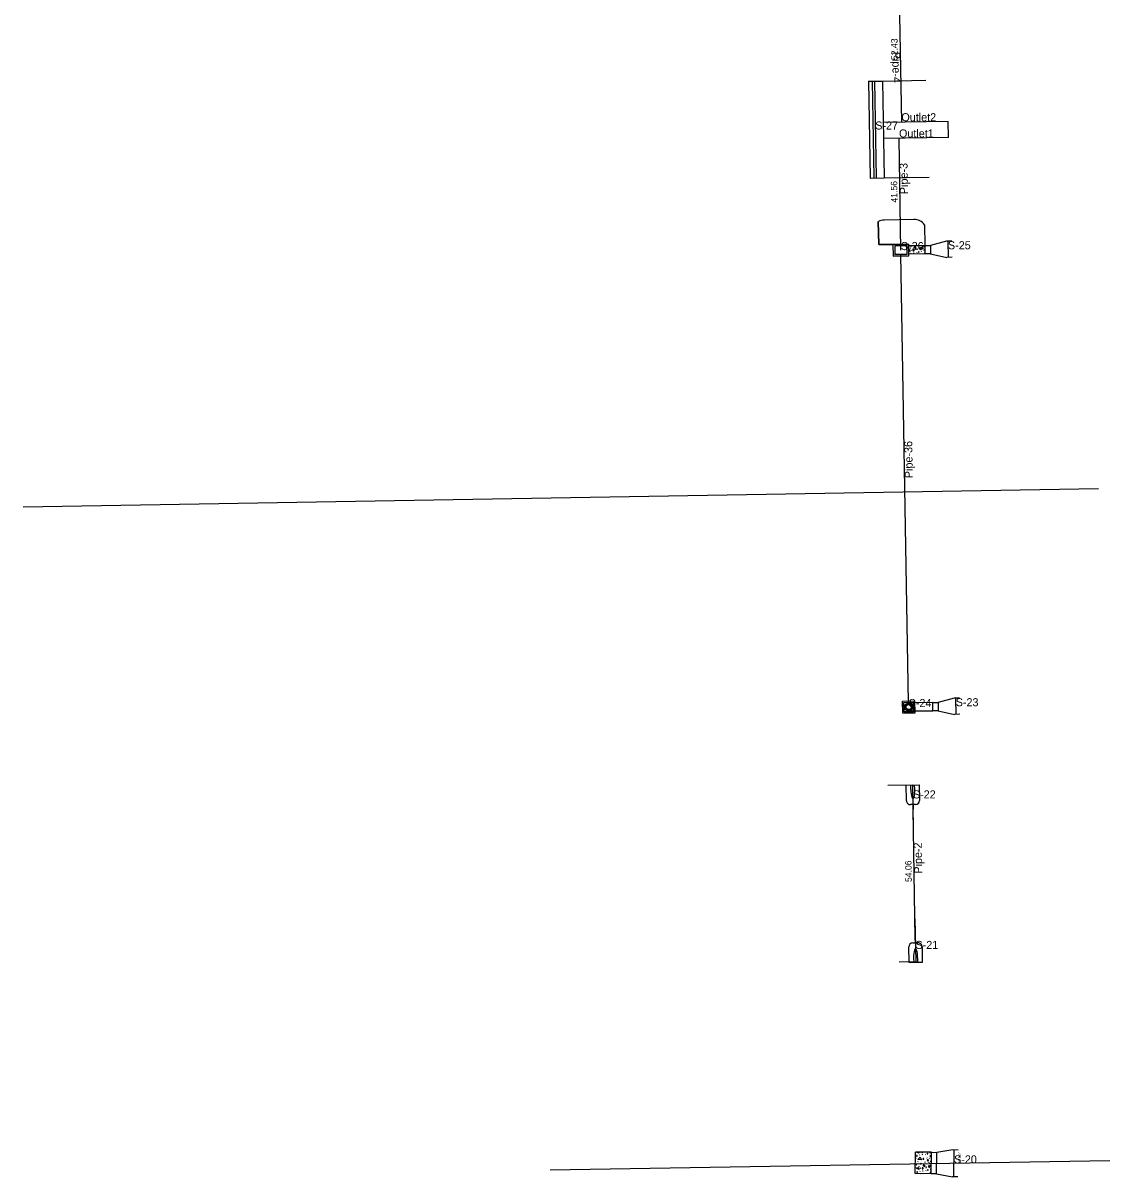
# Model space of a CAD drawing. Extents: x 925371 to 925937, y 853654 to 858024.
# Drawn here: x 925428.5 to 925832.9, y 854923.1 to 855352.2 of the extents above; entities that cross this region are included whole.
import ezdxf

# ---------------------------------------------------------------- set-up
doc = ezdxf.new("R2010")
doc.units = 0
for name, color, linetype in [('DitchPavt', 7, 'Continuous'), ('Endwall', 7, 'Continuous'), ('GPKDrBack_dp', 7, 'Continuous'), ('GPKDrBottom_dp', 7, 'Continuous'), ('GPKDrCellIns_dp', 7, 'Continuous'), ('GPKDrCentroid_dp', 7, 'Continuous'), ('GPKDrFront_dp', 7, 'Continuous'), ('GPKDrPipe_dp', 7, 'Continuous'), ('GPKDrPipeCir_dp', 7, 'Continuous'), ('InletBottomP', 7, 'Continuous'), ('InletClosedFlume', 7, 'Continuous'), ('InletDBI', 7, 'Continuous'), ('Manhole', 7, 'Continuous'), ('MES', 7, 'Continuous'), ('Miscellaneous5', 7, 'Continuous'), ('Miscellaneous6', 7, 'Continuous'), ('NonPlottingEle_dp', 7, 'Continuous'), ('PipeCulvert', 7, 'Continuous'), ('PipeCulvertSS', 7, 'Continuous'), ('Scratch1_dp', 7, 'Continuous')]:
    doc.layers.add(name, color=color, linetype=linetype)

msp = doc.modelspace()

# ---------------------------------------------------------------- linework, layer by layer
at = {"layer": 'DitchPavt'}
for p, q in [((925759.95, 855279.17), (925748.95, 855278.98)), ((925764.11, 855269.46), (925763.98, 855277.23)), ((925752.19, 855269.91), (925758.02, 855270.01)), ((925758.02, 855270.01), (925758.03, 855269.36)), ((925766.11, 855269.5), (925758.03, 855269.36)), ((925758.03, 855269.36), (925764.11, 855269.46)), ((925759.2, 855269.33), (925759.24, 855269.38)), ((925758.4, 855267.29), (925758.06, 855267.45)), ((925766.16, 855266.46), (925758.08, 855266.32)), ((925758.49, 855268.38), (925758.65, 855268.48)), ((925758.78, 855266.51), (925758.93, 855266.63)), ((925760.02, 855266.6), (925759.82, 855266.69)), ((925761.02, 855266.74), (925761.16, 855266.84)), ((925761.1, 855267.94), (925761.25, 855268.04)), ((925761.28, 855268.21), (925761.43, 855268.31)), ((925762.55, 855267.91), (925762.35, 855268)), ((925762.86, 855267.24), (925762.64, 855267.33)), ((925763.36, 855268.25), (925763.51, 855268.38)), ((925767, 855099.49), (925759, 855099.35)), ((925767, 855099.49), (925759, 855099.35)), ((925759, 855099.35), (925759.06, 855096.31)), ((925767.05, 855096.45), (925767, 855099.49)), ((925767.05, 855096.45), (925767, 855099.49)), ((925767.05, 855096.45), (925759.06, 855096.31)), ((925759.06, 855096.31), (925767.05, 855096.45)), ((925766.48, 854932.22), (925760.6, 854932.31)), ((925761.66, 854931.94), (925760.91, 854932.3)), ((925761.62, 854932.29), (925761.66, 854931.94)), ((925762.03, 854931.16), (925762.18, 854931.27)), ((925762.25, 854932.23), (925762.27, 854932.28)), ((925763.28, 854931.25), (925763.07, 854931.34)), ((925764.28, 854931.39), (925764.41, 854931.48)), ((925766.11, 854931.89), (925765.89, 854931.98)), ((925760.59, 854926.7), (925760.74, 854926.83)), ((925760.7, 854930.05), (925760.83, 854930.14)), ((925761.45, 854928.68), (925761.59, 854928.78)), ((925761.85, 854926.94), (925762.01, 854927.04)), ((925764.3, 854928.42), (925764.07, 854928.51)), ((925764.45, 854926.5), (925764.61, 854926.6)), ((925764.64, 854926.77), (925764.79, 854926.86)), ((925764.96, 854930.01), (925764.74, 854930.1)), ((925765.44, 854928.41), (925765.23, 854928.5)), ((925765.83, 854929.91), (925765.61, 854930)), ((925765.91, 854926.46), (925765.7, 854926.55)), ((925765.83, 854928.18), (925765.99, 854928.29)), ((925766.21, 854925.79), (925765.99, 854925.88)), ((925762.13, 854925.07), (925762.29, 854925.18)), ((925763.38, 854925.15), (925763.18, 854925.24)), ((925764.38, 854925.29), (925764.52, 854925.39))]:
    msp.add_line(p, q, dxfattribs=at)
for points in [[(925758.02, 855270.01), (925746.89, 855269.82), (925746.74, 855278.43)], [(925746.74, 855278.43), (925746.89, 855269.82), (925752.19, 855269.91)], [(925759.11, 855269.38), (925759.12, 855269.36), (925759.2, 855269.33), (925759.17, 855269.33)], [(925763.73, 855269.07), (925763.76, 855269.1), (925763.79, 855269.19), (925763.75, 855269.29), (925763.7, 855269.32), (925763.6, 855269.28), (925763.58, 855269.16), (925763.61, 855269.1), (925763.67, 855269.07), (925763.73, 855269.07)], [(925758.05, 855267.92), (925758.33, 855268.04), (925758.4, 855267.29)], [(925758.99, 855267.58), (925759.04, 855267.71), (925758.97, 855267.7), (925758.9, 855267.67), (925758.93, 855267.59), (925758.99, 855267.58)], [(925759.68, 855267.53), (925759.95, 855267.47), (925760.04, 855267.58), (925760.04, 855267.66), (925760.03, 855267.83), (925759.85, 855267.91), (925759.68, 855267.86), (925759.63, 855267.75), (925759.63, 855267.62), (925759.68, 855267.53)], [(925760.7, 855268.3), (925760.08, 855268.6), (925760.44, 855269.07), (925760.7, 855268.3)], [(925761.75, 855266.97), (925761.86, 855267.03), (925761.88, 855267.13), (925761.83, 855267.19), (925761.8, 855267.19), (925761.7, 855267.16), (925761.66, 855267.09), (925761.71, 855267.03), (925761.75, 855266.97)], [(925762.12, 855268.29), (925762.18, 855268.34), (925762.21, 855268.42), (925762.18, 855268.48), (925762.12, 855268.49), (925762.04, 855268.48), (925761.96, 855268.44), (925762, 855268.35), (925762.03, 855268.29), (925762.12, 855268.29)], [(925762.5, 855268.11), (925762.21, 855268.63), (925762.78, 855268.89), (925762.5, 855268.11)], [(925764.14, 855267.58), (925763.66, 855267.82), (925764.14, 855268.01)], [(925764.1, 855266.42), (925764.09, 855266.45), (925764, 855266.54), (925763.85, 855266.54), (925763.78, 855266.44), (925763.78, 855266.42)], [(925766.36, 854924.18), (925760.48, 854924.27), (925760.6, 854932.31)], [(925760.96, 854930.82), (925761.1, 854930.77), (925761.22, 854930.8), (925761.24, 854930.91), (925761.22, 854930.99), (925761.12, 854931.08), (925760.98, 854931.08), (925760.91, 854930.99), (925760.91, 854930.91), (925760.96, 854930.82)], [(925762.86, 854929.36), (925761.48, 854929.53), (925762.35, 854930.42), (925762.86, 854929.36)], [(925762.17, 854932.28), (925762.18, 854932.24), (925762.25, 854932.23)], [(925762.89, 854932.27), (925762.89, 854932.27), (925762.93, 854932.18)], [(925762.93, 854932.18), (925763.2, 854932.12), (925763.29, 854932.23), (925763.29, 854932.27)], [(925765.01, 854931.62), (925765.11, 854931.68), (925765.13, 854931.78), (925765.08, 854931.84), (925765.05, 854931.84), (925764.96, 854931.81), (925764.91, 854931.74), (925764.96, 854931.68), (925765.01, 854931.62)], [(925766.01, 854930.7), (925766.12, 854930.67), (925766.19, 854930.76), (925766.18, 854930.86), (925766.1, 854930.95), (925766.02, 854930.92), (925765.97, 854930.88), (925765.94, 854930.82), (925765.94, 854930.79), (925766.01, 854930.7)], [(925760.97, 854927.52), (925761, 854927.55), (925761.03, 854927.64), (925760.98, 854927.74), (925760.93, 854927.77), (925760.84, 854927.73), (925760.81, 854927.61), (925760.84, 854927.55), (925760.9, 854927.52), (925760.97, 854927.52)], [(925761.76, 854925.84), (925760.89, 854926.27), (925761.69, 854926.59), (925761.76, 854925.84)], [(925762.35, 854926.13), (925762.39, 854926.26), (925762.33, 854926.26), (925762.25, 854926.23), (925762.29, 854926.15), (925762.35, 854926.13)], [(925762.55, 854927.89), (925762.65, 854927.98), (925762.64, 854928.08), (925762.53, 854928.14), (925762.43, 854928.04), (925762.46, 854927.98), (925762.48, 854927.92), (925762.55, 854927.89), (925762.52, 854927.89)], [(925763.04, 854926.08), (925763.3, 854926.03), (925763.4, 854926.14), (925763.39, 854926.22), (925763.39, 854926.39), (925763.2, 854926.46), (925763.03, 854926.41), (925762.99, 854926.3), (925762.99, 854926.18), (925763.04, 854926.08)], [(925763.43, 854929.67), (925763.54, 854929.64), (925763.65, 854929.72), (925763.61, 854929.83), (925763.57, 854929.91), (925763.49, 854929.9), (925763.38, 854929.87), (925763.33, 854929.78), (925763.38, 854929.68), (925763.43, 854929.67)], [(925764.06, 854926.85), (925763.44, 854927.15), (925763.79, 854927.63), (925764.06, 854926.85)], [(925765.13, 854928.95), (925765.29, 854929), (925765.36, 854929.19), (925765.25, 854929.4), (925765.09, 854929.4), (925764.97, 854929.32), (925764.95, 854929.24), (925764.99, 854929.1), (925765.02, 854928.99), (925765.13, 854928.95)], [(925765.48, 854926.84), (925765.54, 854926.89), (925765.57, 854926.97), (925765.54, 854927.03), (925765.47, 854927.05), (925765.4, 854927.03), (925765.32, 854927), (925765.35, 854926.9), (925765.38, 854926.84), (925765.48, 854926.84)], [(925765.86, 854926.66), (925765.57, 854927.19), (925766.14, 854927.45), (925765.86, 854926.66)], [(925766.26, 854928.73), (925766.35, 854928.73), (925766.37, 854928.81), (925766.35, 854928.89), (925766.26, 854928.95), (925766.21, 854928.92), (925766.16, 854928.86), (925766.16, 854928.76), (925766.26, 854928.73)], [(925766.36, 854924.18), (925760.48, 854924.27)], [(925761.06, 854924.72), (925761.2, 854924.68), (925761.33, 854924.71), (925761.34, 854924.82), (925761.32, 854924.9), (925761.23, 854924.99), (925761.09, 854924.99), (925761.01, 854924.89), (925761.01, 854924.82), (925761.06, 854924.72)], [(925762.38, 854924.24), (925762.46, 854924.32), (925762.5, 854924.24)], [(925765.11, 854925.53), (925765.22, 854925.59), (925765.23, 854925.68), (925765.18, 854925.75), (925765.15, 854925.75), (925765.06, 854925.71), (925765.01, 854925.65), (925765.06, 854925.59), (925765.11, 854925.53)], [(925766.11, 854924.6), (925766.22, 854924.58), (925766.3, 854924.67), (925766.28, 854924.76), (925766.2, 854924.86), (925766.12, 854924.82), (925766.08, 854924.79), (925766.05, 854924.73), (925766.05, 854924.7), (925766.11, 854924.6)]]:
    msp.add_lwpolyline(points, dxfattribs=at)
for centre, start, end in [((925749.03, 855273.98), 90.9573, 117.2461), ((925760.03, 855274.17), 37.844, 90.9573)]:
    msp.add_arc(centre, 5, start, end, dxfattribs=at)
at = {"layer": 'Endwall'}
for p, q in [((925743.1, 855330.6), (925748.35, 855330.68)), ((925743.1, 855330.6), (925743.72, 855294.6)), ((925744.44, 855330.62), (925745.05, 855294.62)), ((925745.27, 855330.63), (925745.88, 855294.64)), ((925748.35, 855330.68), (925748.96, 855294.69)), ((925743.72, 855294.6), (925748.96, 855294.69))]:
    msp.add_line(p, q, dxfattribs=at)
at = {"layer": 'GPKDrBack_dp'}
for p, q in [((925744.74, 855312.62), (925744.74, 855312.62)), ((925755.1, 855269.96), (925755.1, 855269.96)), ((925758.06, 855267.84), (925758.06, 855267.84)), ((925766.14, 855267.98), (925766.14, 855267.98)), ((925759.53, 855097.84), (925759.53, 855097.84)), ((925759.78, 855097.85), (925759.78, 855097.85)), ((925769.03, 855098), (925769.03, 855098)), ((925759.52, 855068.87), (925759.52, 855068.87)), ((925760.64, 855002.82), (925760.64, 855002.82)), ((925768.42, 854928.17), (925768.42, 854928.17))]:
    msp.add_line(p, q, dxfattribs=at)
at = {"layer": 'GPKDrBottom_dp'}
for p, q in [((925745.58, 855312.64), (925745.58, 855312.64)), ((925752.86, 855269.25), (925752.86, 855269.25)), ((925755.11, 855269.29), (925755.11, 855269.29)), ((925757.36, 855269.33), (925757.36, 855269.33)), ((925752.89, 855267.75), (925752.89, 855267.75)), ((925752.92, 855266.25), (925752.92, 855266.25)), ((925755.14, 855267.79), (925755.14, 855267.79)), ((925755.16, 855266.29), (925755.16, 855266.29)), ((925757.39, 855267.83), (925757.39, 855267.83)), ((925757.41, 855266.33), (925757.41, 855266.33)), ((925772.64, 855268.09), (925772.64, 855268.09)), ((925756.25, 855099.54), (925756.25, 855099.54)), ((925756.28, 855097.79), (925756.28, 855097.79)), ((925757.03, 855097.8), (925757.03, 855097.8)), ((925757.31, 855098.51), (925757.31, 855098.51)), ((925758, 855099.57), (925758, 855099.57)), ((925758.01, 855098.82), (925758.01, 855098.82)), ((925758.03, 855097.82), (925758.03, 855097.82)), ((925758.03, 855097.82), (925758.03, 855097.82)), ((925758.72, 855098.53), (925758.72, 855098.53)), ((925759.03, 855097.83), (925759.03, 855097.83)), ((925759.75, 855099.6), (925759.75, 855099.6)), ((925759.78, 855097.85), (925759.78, 855097.85)), ((925775.53, 855098.11), (925775.53, 855098.11)), ((925756.31, 855096.04), (925756.31, 855096.04)), ((925757.33, 855097.1), (925757.33, 855097.1)), ((925758.05, 855096.82), (925758.05, 855096.82)), ((925758.06, 855096.07), (925758.06, 855096.07)), ((925758.75, 855097.12), (925758.75, 855097.12)), ((925759.81, 855096.1), (925759.81, 855096.1)), ((925759.61, 855063.84), (925759.61, 855063.84)), ((925760.56, 855007.85), (925760.56, 855007.85)), ((925774.92, 854928.08), (925774.92, 854928.08))]:
    msp.add_line(p, q, dxfattribs=at)
at = {"layer": 'GPKDrCellIns_dp'}
for p, q in [((925745.58, 855312.64), (925745.58, 855312.64)), ((925755.14, 855267.79), (925755.14, 855267.79)), ((925772.64, 855268.09), (925772.64, 855268.09)), ((925758.03, 855097.82), (925758.03, 855097.82)), ((925758.03, 855097.82), (925758.03, 855097.82)), ((925775.53, 855098.11), (925775.53, 855098.11)), ((925759.61, 855063.84), (925759.61, 855063.84)), ((925760.56, 855007.85), (925760.56, 855007.85)), ((925774.92, 854928.08), (925774.92, 854928.08))]:
    msp.add_line(p, q, dxfattribs=at)
at = {"layer": 'GPKDrCentroid_dp'}
msp.add_line((925758.03, 855097.82), (925758.03, 855097.82), dxfattribs=at)
at = {"layer": 'GPKDrFront_dp'}
for p, q in [((925745.58, 855312.64), (925745.58, 855312.64)), ((925752.22, 855267.74), (925752.22, 855267.74)), ((925755.18, 855265.62), (925755.18, 855265.62)), ((925774.14, 855268.11), (925774.14, 855268.11)), ((925756.28, 855097.79), (925756.28, 855097.79)), ((925756.53, 855097.79), (925756.53, 855097.79)), ((925777.03, 855098.14), (925777.03, 855098.14)), ((925759.65, 855061.55), (925759.65, 855061.55)), ((925760.52, 855010.14), (925760.52, 855010.14)), ((925776.42, 854928.06), (925776.42, 854928.06))]:
    msp.add_line(p, q, dxfattribs=at)
at = {"layer": 'GPKDrPipe_dp'}
for p, q in [((925745.24, 855312.63), (925745.24, 855312.63)), ((925755.11, 855269.29), (925755.11, 855269.29)), ((925752.89, 855267.75), (925752.89, 855267.75)), ((925755.16, 855266.29), (925755.16, 855266.29)), ((925757.39, 855267.83), (925757.39, 855267.83)), ((925756.28, 855097.79), (925756.28, 855097.79)), ((925758, 855099.57), (925758, 855099.57)), ((925759.78, 855097.85), (925759.78, 855097.85)), ((925758.06, 855096.07), (925758.06, 855096.07)), ((925759.67, 855059.87), (925759.67, 855059.87)), ((925760.49, 855011.82), (925760.49, 855011.82))]:
    msp.add_line(p, q, dxfattribs=at)
at = {"layer": 'GPKDrPipeCir_dp'}
msp.add_circle((925758.03, 855097.82), 0.958, dxfattribs=at)
at = {"layer": 'InletBottomP'}
for points in [[(925760.24, 855100.1), (925760.32, 855095.6), (925755.82, 855095.53), (925755.74, 855100.03)], [(925756.25, 855099.54), (925759.75, 855099.6), (925759.81, 855096.1), (925756.31, 855096.04)]]:
    msp.add_lwpolyline(points, close=True, dxfattribs=at)
at = {"layer": 'InletClosedFlume'}
for p, q in [((925772.09, 855271.08), (925766.11, 855269.5)), ((925766.11, 855269.5), (925766.16, 855266.46)), ((925774.09, 855271.11), (925772.09, 855271.08)), ((925772.59, 855271.09), (925772.69, 855265.09)), ((925766.16, 855266.46), (925772.19, 855265.08)), ((925774.19, 855265.11), (925772.19, 855265.08)), ((925774.98, 855101.1), (925769, 855099.52)), ((925769, 855099.52), (925769.05, 855096.48)), ((925776.98, 855101.14), (925774.98, 855101.1)), ((925775.48, 855101.11), (925775.58, 855095.11)), ((925769.05, 855096.48), (925775.08, 855095.11)), ((925777.08, 855095.14), (925775.08, 855095.11)), ((925768.36, 854924.15), (925768.48, 854932.19)), ((925774.49, 854933.09), (925768.48, 854932.19)), ((925776.49, 854933.06), (925774.49, 854933.09)), ((925774.85, 854923.08), (925774.99, 854933.08)), ((925768.36, 854924.15), (925774.35, 854923.09)), ((925776.35, 854923.06), (925774.35, 854923.09))]:
    msp.add_line(p, q, dxfattribs=at)
for points in [[(925766.16, 855266.46), (925764.16, 855266.42), (925764.11, 855269.46), (925766.11, 855269.5)], [(925769.05, 855096.48), (925767.05, 855096.45), (925767, 855099.49), (925769, 855099.52)], [(925768.36, 854924.15), (925766.36, 854924.18), (925766.48, 854932.22), (925768.46, 854932.19)]]:
    msp.add_lwpolyline(points, dxfattribs=at)
at = {"layer": 'InletDBI'}
for p, q in [((925758.02, 855270.01), (925752.19, 855269.91)), ((925752.19, 855269.91), (925752.26, 855265.58)), ((925757.36, 855269.52), (925752.86, 855269.44)), ((925752.86, 855269.44), (925752.92, 855266.07)), ((925757.36, 855269.33), (925752.86, 855269.25)), ((925757.42, 855266.14), (925757.36, 855269.52)), ((925758.09, 855265.67), (925758.02, 855270.01)), ((925752.26, 855265.58), (925758.09, 855265.67)), ((925752.92, 855266.25), (925757.41, 855266.33)), ((925752.92, 855266.07), (925757.42, 855266.14))]:
    msp.add_line(p, q, dxfattribs=at)
at = {"layer": 'Manhole'}
for p, q in [((925756.98, 855097.82), (925756.78, 855097.82)), ((925756.98, 855097.77), (925756.78, 855097.77)), ((925757.26, 855098.53), (925757.11, 855098.67)), ((925757.29, 855098.57), (925757.15, 855098.7)), ((925757.99, 855098.87), (925757.98, 855099.07)), ((925758.04, 855098.87), (925758.03, 855099.07)), ((925758.88, 855098.73), (925758.74, 855098.59)), ((925758.92, 855098.7), (925758.78, 855098.55)), ((925759.28, 855097.86), (925759.08, 855097.86)), ((925759.28, 855097.81), (925759.08, 855097.81)), ((925757.28, 855097.08), (925757.14, 855096.94)), ((925757.32, 855097.04), (925757.18, 855096.9)), ((925758.02, 855096.57), (925758.02, 855096.76)), ((925758.08, 855096.57), (925758.07, 855096.76)), ((925758.91, 855096.93), (925758.77, 855097.07)), ((925758.95, 855096.97), (925758.8, 855097.1))]:
    msp.add_line(p, q, dxfattribs=at)
for radius in [1.5, 1.25, 1.05, 1]:
    msp.add_circle((925758.03, 855097.82), radius, dxfattribs=at)
at = {"layer": 'MES'}
for p, q in [((925757.06, 855068.83), (925761.98, 855068.91)), ((925757.16, 855063.01), (925757.06, 855068.83)), ((925758.81, 855067.11), (925758.82, 855068.85)), ((925760.3, 855067.13), (925760.23, 855068.88)), ((925761.98, 855068.91), (925762.08, 855063.09)), ((925760.61, 855061.56), (925758.69, 855061.53)), ((925759.65, 855061.55), (925759.67, 855059.87)), ((925760.52, 855010.13), (925760.49, 855011.82)), ((925758.19, 855002.77), (925758.09, 855008.59)), ((925759.56, 855010.12), (925761.48, 855010.15)), ((925763.01, 855008.68), (925763.1, 855002.86)), ((925759.87, 855004.55), (925759.94, 855002.8)), ((925761.36, 855004.57), (925761.35, 855002.83)), ((925763.1, 855002.86), (925758.19, 855002.77))]:
    msp.add_line(p, q, dxfattribs=at)
for centre, start, end in [((925758.66, 855063.03), 180.9741, 270.9741), ((925760.58, 855063.06), 270.9741, 0.9741), ((925759.59, 855008.62), 90.9741, 180.9741), ((925761.51, 855008.65), 0.9741, 90.9741)]:
    msp.add_arc(centre, 1.5, start, end, dxfattribs=at)
for centre, major_axis in [((925759.56, 855066.84), (0.05, -3)), ((925760.61, 855004.85), (-0.05, 3))]:
    msp.add_ellipse(centre, major_axis=major_axis, ratio=0.25, start_param=4.617261, end_param=7.949056, dxfattribs=at)
at = {"layer": 'Miscellaneous5'}
msp.add_line((925828.66, 855179.03), (925428.53, 855172.22), dxfattribs=at)
at = {"layer": 'Miscellaneous6'}
msp.add_line((925832.91, 854929.06), (925624.63, 854925.52), dxfattribs=at)
at = {"layer": 'NonPlottingEle_dp'}
for points in [[(925759.8, 855052.75), (925759.52, 855068.75), (925750.25, 855068.59)], [(925760.37, 855019.01), (925760.64, 855003.01), (925754.54, 855002.91)]]:
    msp.add_lwpolyline(points, dxfattribs=at)
at = {"layer": 'PipeCulvert'}
for p, q in [((925772.73, 855315.65), (925748.62, 855315.24)), ((925772.84, 855309.65), (925772.73, 855315.65)), ((925772.84, 855309.65), (925748.72, 855309.24)), ((925760.49, 855011.82), (925759.67, 855059.87))]:
    msp.add_line(p, q, dxfattribs=at)
at = {"layer": 'PipeCulvertSS'}
for p, q in [((925754.44, 855367.79), (925755.33, 855315.37)), ((925755.14, 855267.79), (925754.43, 855309.35)), ((925758, 855099.57), (925755.16, 855266.29))]:
    msp.add_line(p, q, dxfattribs=at)
at = {"layer": 'Scratch1_dp'}
for p, q in [((925748.35, 855330.68), (925764.37, 855330.96)), ((925748.96, 855294.69), (925765.68, 855294.97)), ((925764.11, 855269.46), (925763.98, 855277.23))]:
    msp.add_line(p, q, dxfattribs=at)
msp.add_lwpolyline([(925759.06, 855096.31), (925759, 855099.35)], dxfattribs=at)

# ---------------------------------------------------------------- texts
at = {"layer": 'NonPlottingEle_dp'}
for s, height, rotation, p in [('52.43', 2.4, 90.9741, (925754, 855338.49)), ('Pipe-4', 3, 270.9741, (925751.89, 855341.53)), ('Pipe-3', 3, 90.9741, (925757.79, 855288.62)), ('41.56', 2.4, 90.9741, (925753.9, 855285.48)), ('Pipe-36', 3, 90.9741, (925759.58, 855182.98)), ('Pipe-2', 3, 90.9739, (925763.08, 855035.89)), ('54.06', 2.4, 90.9741, (925759.2, 855032.75)), ('16.627', 1, 90.9741, (925777.39, 854928.06))]:
    msp.add_text(s, height=height, rotation=rotation, dxfattribs=at).set_placement(p)
for s, p in [('Outlet2', (925755.32, 855315.7)), ('S-27', (925745.58, 855312.64)), ('Outlet1', (925754.43, 855309.68)), ('S-26', (925755.14, 855267.79)), ('S-25', (925772.64, 855268.09)), ('S-24', (925758.03, 855097.82)), ('S-23', (925775.53, 855098.11)), ('S-22', (925759.61, 855063.84)), ('S-21', (925760.56, 855007.85)), ('S-20', (925774.92, 854928.08))]:
    msp.add_text(s, height=3, dxfattribs=at).set_placement(p)

doc.saveas('drawing.dxf')
